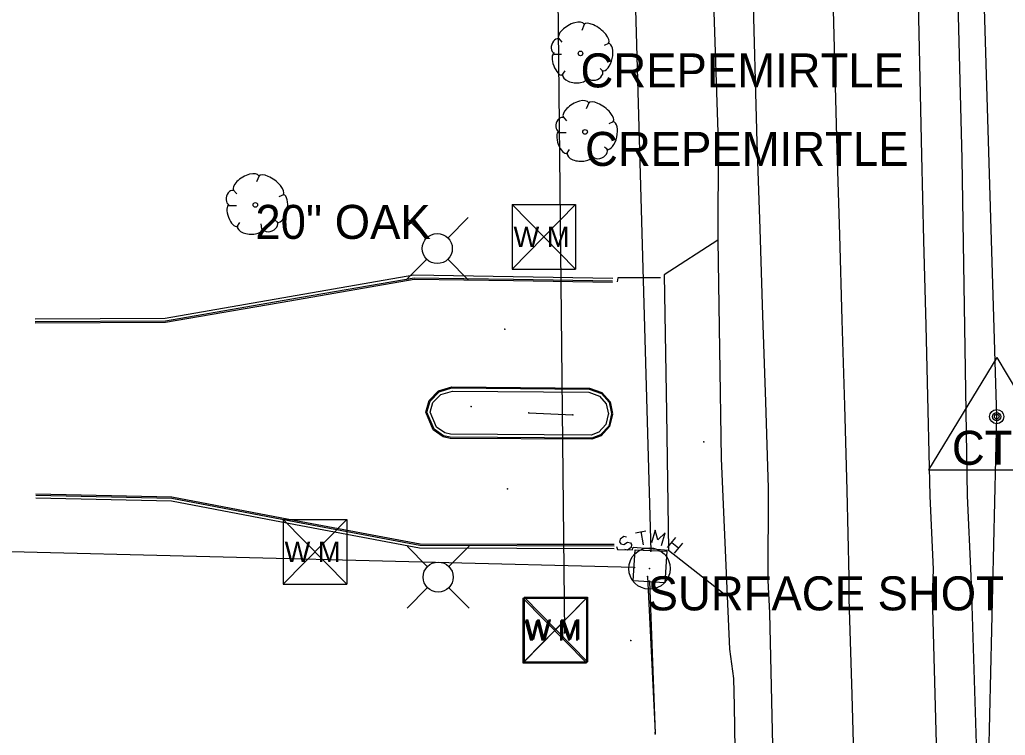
# Model space of a CAD drawing. Extents: x 1930288 to 1941089, y 588389 to 611475.
# Drawn here: x 1930778.4 to 1930923.3, y 597126 to 597231.2 of the extents above; entities that cross this region are included whole.
import ezdxf

# ---------------------------------------------------------------- set-up
doc = ezdxf.new("R2010")
doc.units = 0
for name, color, linetype in [('S_BASELINE', 7, 'Continuous'), ('S_CURB', 7, 'Continuous'), ('S_DRIVEWAY', 7, 'Continuous'), ('S_DROP_INLET', 7, 'Continuous'), ('S_EDGE_PAVEMENT', 7, 'Continuous'), ('S_GRD_PT_SYM', 7, 'Continuous'), ('S_MISC_TOPO_POINT', 7, 'Continuous'), ('S_MSC_PT_SYM', 7, 'Continuous'), ('S_PAVEMENT_CROWN', 7, 'Continuous'), ('S_PRIMARY_CTL', 7, 'Continuous'), ('S_SHOULDER', 7, 'Continuous'), ('S_SIGN', 7, 'Continuous'), ('S_STORM_SEWER', 7, 'Continuous'), ('S_TREE', 7, 'Continuous'), ('S_TREE_ANNOT', 7, 'Continuous'), ('S_UTILITY_POLE', 7, 'Continuous'), ('S_UTL_PT_SYM', 7, 'Continuous'), ('S_WATER_UTILITIES', 7, 'Continuous')]:
    doc.layers.add(name, color=color, linetype=linetype)

msp = doc.modelspace()

# ---------------------------------------------------------------- linework, layer by layer
at = {"layer": 'S_BASELINE'}
for p, q in [((1930922.05, 597172.86), (1930894.27, 598110.49)), ((1930901.19, 596273.28), (1930922.05, 597172.86))]:
    msp.add_line(p, q, dxfattribs=at)
at = {"layer": 'S_CURB'}
for points in [[(1930865.59, 597193.19), (1930850.97, 597193.41), (1930836.36, 597193.64), (1930818.08, 597190.46), (1930799.79, 597187.28), (1930780.69, 597187.21)], [(1930865.58, 597192.79), (1930850.99, 597193.01), (1930836.4, 597193.24), (1930818.11, 597190.06), (1930799.83, 597186.88), (1930780.69, 597186.81)], [(1930865.4, 597173.25), (1930865, 597171.47), (1930863.8, 597170.19), (1930862.5, 597169.7), (1930841.71, 597169.82), (1930840.71, 597170.04), (1930839.32, 597171), (1930838.27, 597173.51), (1930838.75, 597175.16), (1930840.06, 597176.53), (1930841.96, 597177.08), (1930862.14, 597176.9), (1930863.93, 597176.26), (1930865.06, 597174.97), (1930865.43, 597173.3)], [(1930864.96, 597173.35), (1930864.59, 597171.69), (1930863.55, 597170.58), (1930862.42, 597170.15), (1930841.76, 597170.27), (1930840.9, 597170.46), (1930839.68, 597171.3), (1930838.75, 597173.54), (1930839.15, 597174.93), (1930840.3, 597176.13), (1930842.03, 597176.63), (1930862.06, 597176.45), (1930863.66, 597175.88), (1930864.65, 597174.76), (1930864.99, 597173.2)], [(1930780.75, 597160.91), (1930800.72, 597160.47), (1930818.96, 597157.01), (1930837.21, 597153.56), (1930851.5, 597153.52), (1930865.79, 597153.48)], [(1930780.76, 597161.31), (1930800.76, 597160.87), (1930819, 597157.41), (1930837.25, 597153.96), (1930851.52, 597153.92), (1930865.79, 597153.89)]]:
    msp.add_lwpolyline(points, dxfattribs=at)
at = {"layer": 'S_DRIVEWAY'}
for points in [[(1930881.06, 597198.79), (1930873.14, 597193.69)], [(1930873.14, 597193.69), (1930873.48, 597173.47), (1930873.81, 597153.25)], [(1930865.58, 597192.59), (1930850.99, 597192.81), (1930836.41, 597193.04), (1930818.13, 597189.86), (1930799.84, 597186.68), (1930780.69, 597186.61)], [(1930872.61, 597193.26), (1930866.36, 597193.26), (1930866.23, 597192.67)], [(1930865.54, 597173.22), (1930865.14, 597171.4), (1930863.89, 597170.06), (1930862.52, 597169.55), (1930841.69, 597169.67), (1930840.65, 597169.9), (1930839.19, 597170.9), (1930838.11, 597173.5), (1930838.61, 597175.24), (1930839.98, 597176.66), (1930841.94, 597177.23), (1930862.17, 597177.05), (1930864.01, 597176.39), (1930865.2, 597175.04), (1930865.58, 597173.33)], [(1930780.77, 597161.51), (1930800.78, 597161.07), (1930819.02, 597157.61), (1930837.27, 597154.16), (1930851.53, 597154.12), (1930865.79, 597154.09)], [(1930866.15, 597153.77), (1930866.28, 597153.32), (1930868.51, 597153.3), (1930868.59, 597153.67), (1930873.81, 597153.25)], [(1930873.81, 597153.25), (1930882.41, 597146.46)]]:
    msp.add_lwpolyline(points, dxfattribs=at)
at = {"layer": 'S_DROP_INLET'}
for points in [[(1930873.28, 597148.41), (1930868.58, 597148.74), (1930868.91, 597153.29), (1930873.56, 597153.06)], [(1930873.56, 597153.06), (1930873.28, 597148.41)]]:
    msp.add_lwpolyline(points, dxfattribs=at)
at = {"layer": 'S_EDGE_PAVEMENT'}
for points in [[(1930883.41, 597333.75), (1930883.95, 597312.79), (1930884.33, 597299.81), (1930884.71, 597286.83), (1930885.08, 597273.84), (1930885.46, 597260.86), (1930886.13, 597237.01), (1930886.8, 597213.16), (1930887.21, 597200.45), (1930887.63, 597187.75), (1930888.05, 597175.05), (1930888.46, 597162.35), (1930888.4, 597148.75), (1930888.66, 597144.03), (1930888.95, 597131.01), (1930889.24, 597118)], [(1930907.71, 597333.22), (1930908.28, 597312.07), (1930908.68, 597299.22), (1930909.07, 597286.37), (1930909.47, 597273.53), (1930909.86, 597260.68), (1930910.44, 597235.98), (1930911.01, 597211.28), (1930911.31, 597198.77), (1930911.61, 597186.25), (1930911.91, 597173.74), (1930912.21, 597161.22), (1930912.7, 597150.37), (1930912.58, 597146.46), (1930912.96, 597132.04), (1930913.35, 597117.63)]]:
    msp.add_lwpolyline(points, dxfattribs=at)
at = {"layer": 'S_GRD_PT_SYM'}
msp.add_lwpolyline([(1930870.73, 597149.38), (1930870.73, 597149.43), (1930870.73, 597149.38), (1930870.68, 597149.38), (1930870.73, 597149.38), (1930870.73, 597149.33), (1930870.73, 597149.38), (1930870.78, 597149.38)], dxfattribs=at)
at = {"layer": 'S_MSC_PT_SYM'}
for points in [[(1930849.74, 597185.73), (1930849.74, 597185.78), (1930849.74, 597185.73), (1930849.69, 597185.73), (1930849.74, 597185.73), (1930849.74, 597185.68), (1930849.74, 597185.73), (1930849.79, 597185.73)], [(1930844.79, 597174.34), (1930844.79, 597174.39), (1930844.79, 597174.34), (1930844.74, 597174.34), (1930844.79, 597174.34), (1930844.79, 597174.29), (1930844.79, 597174.34), (1930844.84, 597174.34)], [(1930853.28, 597173.4), (1930853.28, 597173.45), (1930853.28, 597173.4), (1930853.23, 597173.4), (1930853.28, 597173.4), (1930853.28, 597173.35), (1930853.28, 597173.4), (1930853.33, 597173.4)], [(1930859.73, 597173.12), (1930859.73, 597173.17), (1930859.73, 597173.12), (1930859.68, 597173.12), (1930859.73, 597173.12), (1930859.73, 597173.07), (1930859.73, 597173.12), (1930859.78, 597173.12)], [(1930879, 597169.17), (1930879, 597169.22), (1930879, 597169.17), (1930878.95, 597169.17), (1930879, 597169.17), (1930879, 597169.12), (1930879, 597169.17), (1930879.05, 597169.17)], [(1930850.12, 597162.24), (1930850.12, 597162.29), (1930850.12, 597162.24), (1930850.07, 597162.24), (1930850.12, 597162.24), (1930850.12, 597162.19), (1930850.12, 597162.24), (1930850.17, 597162.24)], [(1930871.19, 597153.07), (1930871.19, 597153.12), (1930871.19, 597153.07), (1930871.14, 597153.07), (1930871.19, 597153.07), (1930871.19, 597153.02), (1930871.19, 597153.07), (1930871.24, 597153.07)], [(1930868.79, 597150.66), (1930868.79, 597150.71), (1930868.79, 597150.66), (1930868.74, 597150.66), (1930868.79, 597150.66), (1930868.79, 597150.61), (1930868.79, 597150.66), (1930868.84, 597150.66)], [(1930870.99, 597148.65), (1930870.99, 597148.7), (1930870.99, 597148.65), (1930870.94, 597148.65), (1930870.99, 597148.65), (1930870.99, 597148.6), (1930870.99, 597148.65), (1930871.04, 597148.65)], [(1930868.28, 597139.95), (1930868.28, 597140), (1930868.28, 597139.95), (1930868.23, 597139.95), (1930868.28, 597139.95), (1930868.28, 597139.9), (1930868.28, 597139.95), (1930868.33, 597139.95)]]:
    msp.add_lwpolyline(points, dxfattribs=at)
at = {"layer": 'S_PAVEMENT_CROWN'}
msp.add_lwpolyline([(1930895.7, 597332.87), (1930896.08, 597311.73), (1930896.38, 597299), (1930896.67, 597286.26), (1930896.97, 597273.52), (1930897.26, 597260.78), (1930897.91, 597236.44), (1930898.56, 597212.1), (1930898.93, 597199.57), (1930899.29, 597187.04), (1930899.66, 597174.51), (1930900.03, 597161.98), (1930900.3, 597149.26), (1930900.31, 597149.02), (1930900.31, 597146.15), (1930900.73, 597131.95), (1930901.14, 597117.75)], dxfattribs=at)
at = {"layer": 'S_PRIMARY_CTL'}
for p, q in [((1930922.05, 597181.56), (1930912.01, 597165.04)), ((1930922.05, 597181.56), (1930931.87, 597165.04)), ((1930912.01, 597165.04), (1930931.87, 597165.04))]:
    msp.add_line(p, q, dxfattribs=at)
for radius in [1.04, 0.609, 0.344]:
    msp.add_circle((1930922.05, 597172.86), radius, dxfattribs=at)
at = {"layer": 'S_SHOULDER'}
for points in [[(1930877.23, 597332.98), (1930878.17, 597312.83), (1930878.53, 597299.75), (1930878.88, 597286.66), (1930879.23, 597273.57), (1930879.58, 597260.49), (1930880.33, 597236.83), (1930881.08, 597213.18), (1930881.06, 597198.79), (1930881.29, 597182.76), (1930881.53, 597166.72), (1930882.41, 597146.46), (1930882.75, 597138.66), (1930883.36, 597134.37), (1930883.43, 597130.36), (1930883.65, 597117.6)], [(1930913.51, 597333.17), (1930914.07, 597311.92), (1930914.47, 597299.07), (1930914.87, 597286.23), (1930915.26, 597273.39), (1930915.66, 597260.55), (1930916.31, 597235.65), (1930916.95, 597210.75), (1930917.33, 597185.99), (1930917.7, 597161.23), (1930918.23, 597149.46), (1930918.38, 597145.09), (1930918.82, 597130.98), (1930919.27, 597116.87)]]:
    msp.add_lwpolyline(points, dxfattribs=at)
at = {"layer": 'S_SIGN'}
msp.add_line((1930853.28, 597173.4), (1930859.73, 597173.12), dxfattribs=at)
at = {"layer": 'S_STORM_SEWER'}
for p, q in [((1930866.47, 597322.17), (1930871.19, 597153.07)), ((1930868.79, 597150.66), (1930327.95, 597164.41)), ((1930868.95, 597155.8), (1930870.47, 597156.08)), ((1930869.73, 597155.96), (1930870.08, 597154.02)), ((1930866.67, 597154.84), (1930866.59, 597154.45)), ((1930866.59, 597154.45), (1930866.78, 597154.18)), ((1930867.21, 597155.22), (1930866.67, 597154.84)), ((1930866.78, 597154.18), (1930867.21, 597154.06)), ((1930867.64, 597155.15), (1930867.21, 597155.22)), ((1930867.21, 597154.06), (1930867.75, 597154.41)), ((1930867.75, 597154.41), (1930868.22, 597154.33)), ((1930868.22, 597154.33), (1930868.37, 597154.06)), ((1930873.64, 597153.6), (1930874.88, 597155.07)), ((1930874.3, 597154.37), (1930875.27, 597153.56)), ((1930875.85, 597154.25), (1930874.61, 597152.78)), ((1930867.75, 597153.25), (1930867.37, 597153.32)), ((1930868.3, 597153.63), (1930867.75, 597153.25)), ((1930868.37, 597154.06), (1930868.3, 597153.63)), ((1930870.73, 597149.38), (1930871.84, 597126.42)), ((1930870.99, 597148.65), (1930871.83, 597126.25))]:
    msp.add_line(p, q, dxfattribs=at)
msp.add_lwpolyline([(1930872.75, 597153.91), (1930873.29, 597155.77), (1930872.25, 597154.76), (1930871.86, 597156.19), (1930871.32, 597154.33)], dxfattribs=at)
msp.add_circle((1930871, 597150.53), 3.05, dxfattribs=at)
at = {"layer": 'S_TREE'}
for p, q in [((1930861.42, 597230.5), (1930861.03, 597229.65)), ((1930857.62, 597228.49), (1930858.12, 597227.91)), ((1930864.98, 597227.71), (1930864.32, 597227.44)), ((1930856.96, 597226.16), (1930858.08, 597226.16)), ((1930864.21, 597223.61), (1930863.74, 597224.03)), ((1930858.12, 597222.99), (1930858.59, 597223.68)), ((1930861.8, 597222.72), (1930861.73, 597223.49)), ((1930862.09, 597218.97), (1930861.7, 597218.12)), ((1930858.29, 597216.95), (1930858.8, 597216.37)), ((1930865.65, 597216.18), (1930865, 597215.91)), ((1930857.63, 597214.63), (1930858.76, 597214.63)), ((1930858.8, 597211.45), (1930859.26, 597212.15)), ((1930864.88, 597212.07), (1930864.41, 597212.5)), ((1930862.48, 597211.18), (1930862.4, 597211.95)), ((1930813.61, 597208.24), (1930813.22, 597207.38)), ((1930809.81, 597206.22), (1930810.31, 597205.64)), ((1930817.17, 597205.45), (1930816.51, 597205.18)), ((1930809.15, 597203.9), (1930810.27, 597203.9)), ((1930810.31, 597200.72), (1930810.78, 597201.42)), ((1930813.99, 597200.45), (1930813.92, 597201.22)), ((1930816.4, 597201.34), (1930815.93, 597201.77))]:
    msp.add_line(p, q, dxfattribs=at)
for centre in [(1930860.86, 597226.26), (1930861.53, 597214.72), (1930813.05, 597203.99)]:
    msp.add_circle(centre, 0.341, dxfattribs=at)
for centre, major_axis, ratio, start_param, end_param in [((1930859.52, 597229.46), (1.86, 1.08), 0.471018, 0, 3.141593), ((1930863.18, 597229.14), (-1.81, 1.36), 0.405113, 3.141593, 6.283186), ((1930857.29, 597227.35), (0.31, 1.03), 0.646762, 0, 3.141593), ((1930864.53, 597225.73), (0.46, 2.04), 0.482994, 3.141593, 6.283185), ((1930857.59, 597224.7), (-0.61, 1.6), 0.420543, 6.283185, 9.424777), ((1930860.05, 597222.92), (-1.83, 0.19), 0.529943, 0, 3.141593), ((1930863.01, 597223.21), (1.09, 0.46), 0.711534, 3.141592, 6.283185), ((1930860.2, 597217.93), (1.86, 1.08), 0.471018, 0, 3.141593), ((1930863.85, 597217.6), (-1.81, 1.36), 0.405113, 3.141593, 6.283186), ((1930857.96, 597215.81), (0.31, 1.03), 0.646762, 0, 3.141593), ((1930865.21, 597214.19), (0.46, 2.04), 0.482994, 3.141593, 6.283185), ((1930858.27, 597213.16), (-0.61, 1.6), 0.420543, 6.283185, 9.424777), ((1930860.73, 597211.38), (-1.83, 0.19), 0.529943, 0, 3.141593), ((1930863.68, 597211.67), (1.09, 0.46), 0.711534, 3.141592, 6.283185), ((1930811.71, 597207.19), (1.86, 1.08), 0.471018, 0, 3.141593), ((1930815.37, 597206.87), (-1.81, 1.36), 0.405113, 3.141593, 6.283186), ((1930809.48, 597205.08), (0.31, 1.03), 0.646762, 0, 3.141593), ((1930816.72, 597203.46), (0.46, 2.04), 0.482994, 3.141593, 6.283185), ((1930809.78, 597202.43), (-0.61, 1.6), 0.420543, 6.283185, 9.424777), ((1930812.24, 597200.65), (-1.83, 0.19), 0.529943, 0, 3.141593), ((1930815.2, 597200.94), (1.09, 0.46), 0.711534, 3.141592, 6.283185)]:
    msp.add_ellipse(centre, major_axis=major_axis, ratio=ratio, start_param=start_param, end_param=end_param, dxfattribs=at)
at = {"layer": 'S_UTILITY_POLE'}
for p, q in [((1930838.2, 597199.15), (1930835.22, 597202.13)), ((1930841.38, 597199.15), (1930844.36, 597202.13)), ((1930838.2, 597195.97), (1930835.22, 597192.99)), ((1930841.38, 597195.97), (1930844.36, 597192.99)), ((1930838.33, 597150.85), (1930835.35, 597153.83)), ((1930841.51, 597150.85), (1930844.49, 597153.83)), ((1930838.33, 597147.67), (1930835.35, 597144.69)), ((1930841.51, 597147.67), (1930844.49, 597144.69))]:
    msp.add_line(p, q, dxfattribs=at)
for centre in [(1930839.8, 597197.57), (1930839.93, 597149.27)]:
    msp.add_circle(centre, 2.21, dxfattribs=at)
at = {"layer": 'S_UTL_PT_SYM'}
for points in [[(1930871.19, 597153.07), (1930871.19, 597153.12), (1930871.19, 597153.07), (1930871.14, 597153.07), (1930871.19, 597153.07), (1930871.19, 597153.02), (1930871.19, 597153.07), (1930871.24, 597153.07)], [(1930868.79, 597150.66), (1930868.79, 597150.71), (1930868.79, 597150.66), (1930868.74, 597150.66), (1930868.79, 597150.66), (1930868.79, 597150.61), (1930868.79, 597150.66), (1930868.84, 597150.66)], [(1930871, 597150.53), (1930871, 597150.58), (1930871, 597150.53), (1930870.95, 597150.53), (1930871, 597150.53), (1930871, 597150.48), (1930871, 597150.53), (1930871.05, 597150.53)], [(1930870.73, 597149.38), (1930870.73, 597149.43), (1930870.73, 597149.38), (1930870.68, 597149.38), (1930870.73, 597149.38), (1930870.73, 597149.33), (1930870.73, 597149.38), (1930870.78, 597149.38)], [(1930870.99, 597148.65), (1930870.99, 597148.7), (1930870.99, 597148.65), (1930870.94, 597148.65), (1930870.99, 597148.65), (1930870.99, 597148.6), (1930870.99, 597148.65), (1930871.04, 597148.65)], [(1930858.51, 597141.08), (1930858.51, 597141.13), (1930858.51, 597141.08), (1930858.46, 597141.08), (1930858.51, 597141.08), (1930858.51, 597141.03), (1930858.51, 597141.08), (1930858.56, 597141.08)], [(1930871.83, 597126.25), (1930871.83, 597126.3), (1930871.83, 597126.25), (1930871.78, 597126.25), (1930871.83, 597126.25), (1930871.83, 597126.2), (1930871.83, 597126.25), (1930871.88, 597126.25)], [(1930871.84, 597126.42), (1930871.84, 597126.47), (1930871.84, 597126.42), (1930871.79, 597126.42), (1930871.84, 597126.42), (1930871.84, 597126.37), (1930871.84, 597126.42), (1930871.89, 597126.42)]]:
    msp.add_lwpolyline(points, dxfattribs=at)
at = {"layer": 'S_WATER_UTILITIES'}
for p, q in [((1930857.41, 597243.98), (1930858.51, 597141.08)), ((1930850.81, 597204.04), (1930860.14, 597204.04)), ((1930850.81, 597204.04), (1930850.81, 597194.54)), ((1930850.81, 597204.04), (1930860.14, 597194.54)), ((1930860.14, 597204.04), (1930850.81, 597194.54)), ((1930860.14, 597204.04), (1930860.14, 597194.54)), ((1930850.81, 597194.54), (1930860.14, 597194.54)), ((1930817.14, 597157.72), (1930826.48, 597157.72)), ((1930817.14, 597157.72), (1930817.14, 597148.23)), ((1930817.14, 597157.72), (1930826.48, 597148.23)), ((1930826.48, 597157.72), (1930817.14, 597148.23)), ((1930826.48, 597157.72), (1930826.48, 597148.23)), ((1930817.14, 597148.23), (1930826.48, 597148.23)), ((1930852.39, 597146.16), (1930861.73, 597146.16)), ((1930852.39, 597146.16), (1930852.39, 597136.67)), ((1930852.39, 597146.16), (1930861.73, 597136.67)), ((1930861.73, 597146.16), (1930852.39, 597136.67)), ((1930852.57, 597146.3), (1930861.91, 597146.3)), ((1930852.57, 597146.3), (1930852.57, 597136.81)), ((1930852.57, 597146.3), (1930861.91, 597136.81)), ((1930861.91, 597146.3), (1930852.57, 597136.81)), ((1930861.73, 597146.16), (1930861.73, 597136.67)), ((1930861.91, 597146.3), (1930861.91, 597136.81)), ((1930852.57, 597136.81), (1930861.91, 597136.81)), ((1930852.39, 597136.67), (1930861.73, 597136.67))]:
    msp.add_line(p, q, dxfattribs=at)

# ---------------------------------------------------------------- texts
at = {"layer": 'S_MISC_TOPO_POINT'}
msp.add_text('SURFACE SHOT', height=5, dxfattribs=at).set_placement((1930870.73, 597144.38))
at = {"layer": 'S_PRIMARY_CTL'}
msp.add_text('CTL', height=5, rotation=360, dxfattribs=at).set_placement((1930915.46, 597165.78))
at = {"layer": 'S_TREE_ANNOT'}
for s, p in [('CREPEMIRTLE', (1930860.86, 597221.26)), ('CREPEMIRTLE', (1930861.53, 597209.72)), ('20" OAK', (1930813.05, 597198.99))]:
    msp.add_text(s, height=5, dxfattribs=at).set_placement(p)
at = {"layer": 'S_WATER_UTILITIES'}
for p in [(1930851.01, 597197.8), (1930817.35, 597151.49), (1930852.6, 597139.93), (1930852.78, 597140.07)]:
    msp.add_text('W M', height=3, rotation=360, dxfattribs=at).set_placement(p)

doc.saveas('drawing.dxf')
